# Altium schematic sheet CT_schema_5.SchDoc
size 582 x 363 mm
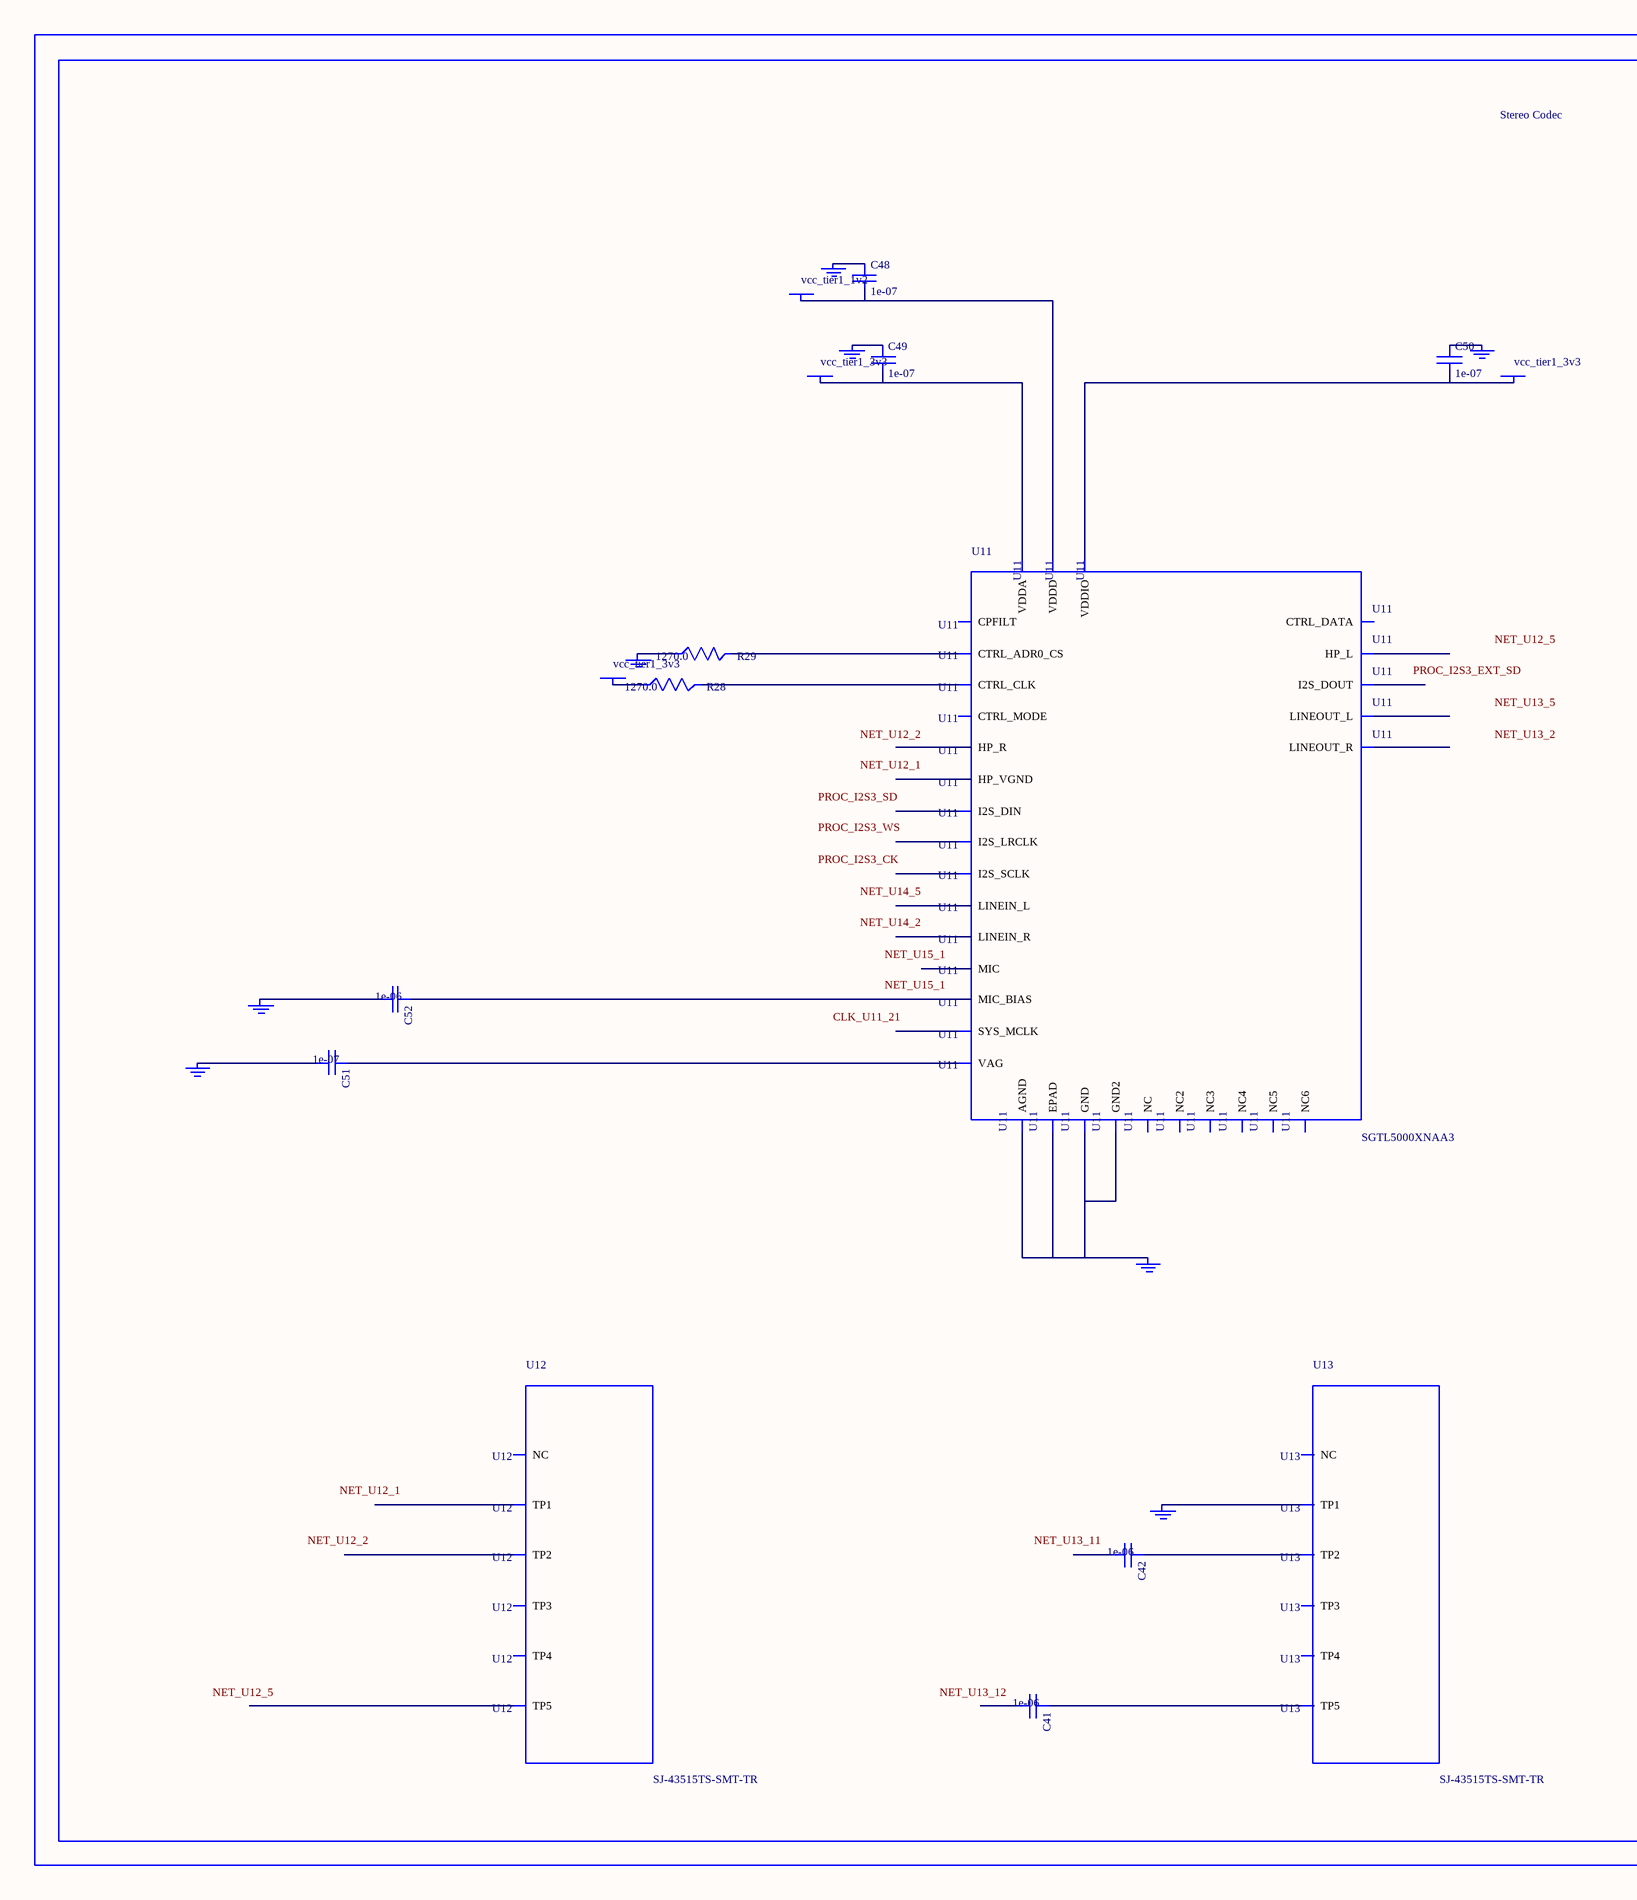
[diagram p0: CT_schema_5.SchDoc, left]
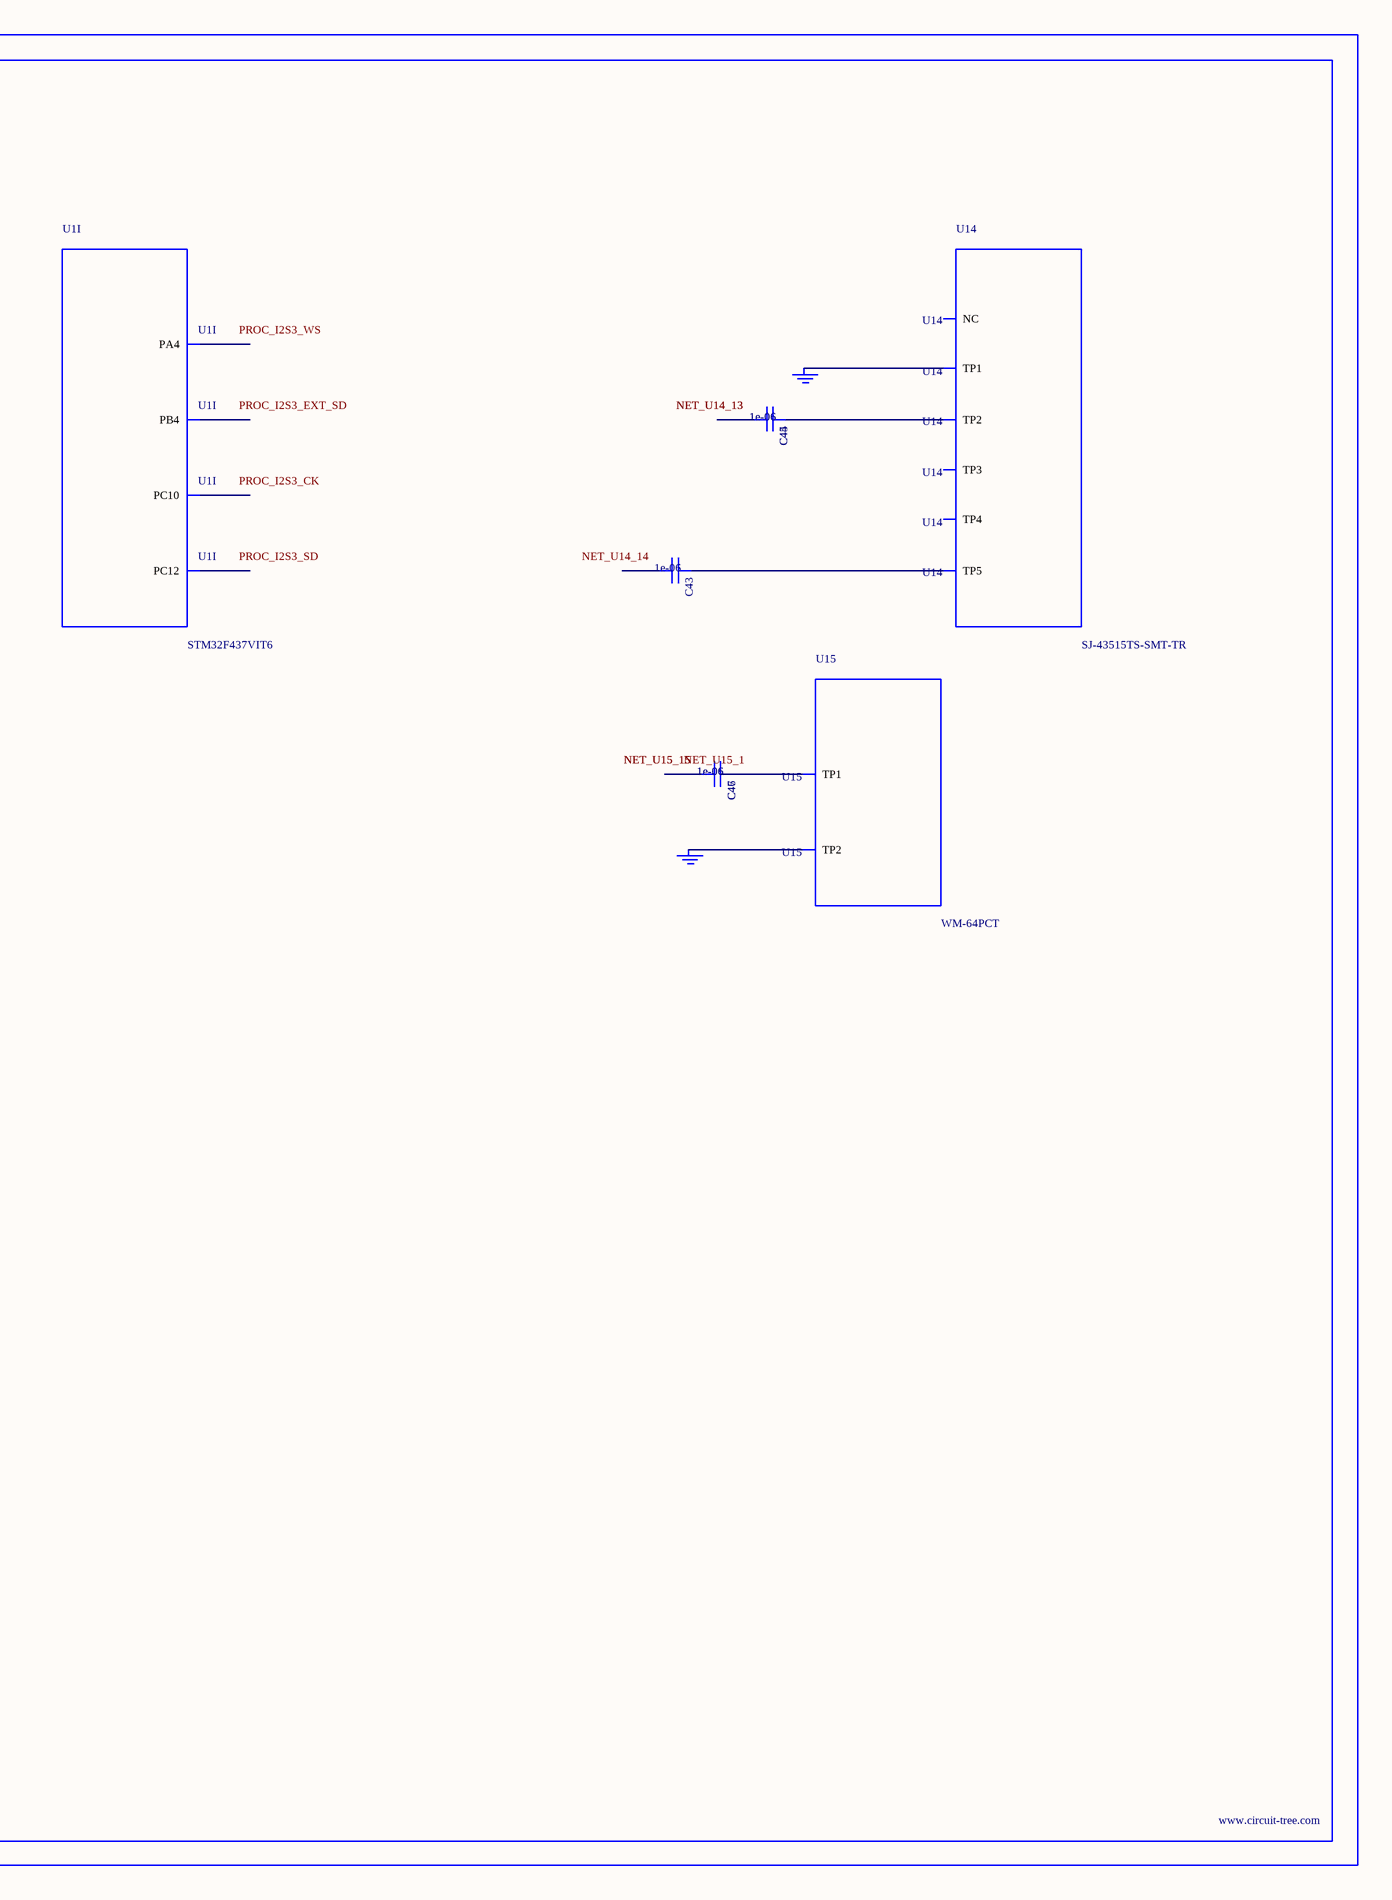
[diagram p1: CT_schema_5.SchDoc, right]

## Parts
BORDER4  (no value)
C41  1e-06  [C0603]
C42  1e-06  [C0603]
C43  1e-06  [C0603]
C44  1e-06  [C0603]
C45  1e-06  [C0603]
C46  1e-06  [C0603]
C47  1e-06  [C0603]
C48  1e-07  [C0402]
C49  1e-07  [C0402]
C50  1e-07  [C0402]
C51  1e-07  [C0402]
C52  1e-06  [C0603]
GND_INSTANCE_4_0  (no value)
GND_INSTANCE_4_1  (no value)
GND_INSTANCE_4_2  (no value)
GND_INSTANCE_4_3  (no value)
GND_INSTANCE_4_4  (no value)
GND_INSTANCE_4_5  (no value)
GND_INSTANCE_4_6  (no value)
GND_INSTANCE_4_7  (no value)
GND_INSTANCE_4_8  (no value)
GND_INSTANCE_4_9  (no value)
GND_INSTANCE_4_10  (no value)
POWER_INSTANCE_4_0  vcc_tier1_3v3
POWER_INSTANCE_4_1  vcc_tier1_3v3
POWER_INSTANCE_4_2  vcc_tier1_3v3
POWER_INSTANCE_4_3  vcc_tier1_1v2
R28  1270.0  [R0603]
R29  1270.0  [R0603]
U1  STM32F437VIT6  [LQFP100]  (part I of 9)
U11  SGTL5000XNAA3  [QFN-32]
U12  SJ-43515TS-SMT-TR  [SJ-43515TS-SMT-TR]
U13  SJ-43515TS-SMT-TR  [SJ-43515TS-SMT-TR]
U14  SJ-43515TS-SMT-TR  [SJ-43515TS-SMT-TR]
U15  WM-64PCT  [WM-64PC]

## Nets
NetC41_1: C41.1 U13.5(TP5)
NetC42_1: C42.1 U13.2(TP2)
NetC43_1: C43.1 U14.5(TP5)
NetC44_1: C44.1 C45.1 U14.2(TP2)
NetC44_2: C44.2 C45.2
NetC46_1: C46.1 C47.1 U15.1(TP1)
NetC46_2: C46.2 C47.2
NetC48_1: C48.1 GND_INSTANCE_4_5.0(GND)
NetC48_2: C48.2 POWER_INSTANCE_4_3.0(PWR) U11.30(VDDD)
NetC49_1: C49.1 GND_INSTANCE_4_1.0(GND)
NetC49_2: C49.2 POWER_INSTANCE_4_0.0(PWR) U11.5(VDDA)
NetC50_1: C50.1 GND_INSTANCE_4_4.0(GND)
NetC50_2: C50.2 POWER_INSTANCE_4_1.0(PWR) U11.20(VDDIO)
NetC51_1: C51.1 U11.10(VAG)
NetC51_2: C51.2 GND_INSTANCE_4_2.0(GND)
NetC52_1: C52.1 U11.16(MIC_BIAS)
NetC52_2: C52.2 GND_INSTANCE_4_3.0(GND)
NetGND_INSTANCE_4_0_0: GND_INSTANCE_4_0.0(GND) U11.1(GND) U11.3(GND2) U11.7(AGND) U11.EXP(EPAD)
NetGND_INSTANCE_4_6_0: GND_INSTANCE_4_6.0(GND) R29.1
NetGND_INSTANCE_4_7_0: GND_INSTANCE_4_7.0(GND) U13.1(TP1)
NetGND_INSTANCE_4_8_0: GND_INSTANCE_4_8.0(GND) GND_INSTANCE_4_9.0(GND) U14.1(TP1)
NetGND_INSTANCE_4_10_0: GND_INSTANCE_4_10.0(GND) U15.2(TP2)
NetPOWER_INSTANCE_4_2_0: POWER_INSTANCE_4_2.0(PWR) R28.1
NetR28_2: R28.2 U11.29(CTRL_CLK)
NetR29_2: R29.2 U11.31(CTRL_ADR0_CS)

Not connected (* = marked no-connect by the designer): C41 2; C42 2; C43 2; U1 29(PA4) 78(PC10) 80(PC12) 90(PB4); U11 2(HP_R) 4(HP_VGND) 6(HP_L) 8(NC) 9(NC2) 11(LINEOUT_R) 12(LINEOUT_L) 13(LINEIN_R) 14(LINEIN_L) 15(MIC) 17(NC3) 18(CPFILT) 19(NC4) 21(SYS_MCLK) 22(NC5) 23(I2S_LRCLK) 24(I2S_SCLK) 25(I2S_DOUT) 26(I2S_DIN) 27(CTRL_DATA) 28(NC6) 32(CTRL_MODE); U12 1(TP1) 2(TP2) 3(TP3) 4(TP4) 5(TP5) 6(NC); U13 3(TP3) 4(TP4) 6(NC); U14 3(TP3) 4(TP4) 6(NC)

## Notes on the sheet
- Labels drawn without touching a wire or pin: CLK_U11_21, NET_U12_1, NET_U12_2, NET_U12_5, NET_U13_2, NET_U13_5, NET_U13_11, NET_U13_12, NET_U14_2, NET_U14_5, NET_U14_14, NET_U15_1, PROC_I2S3_CK, PROC_I2S3_EXT_SD, PROC_I2S3_SD, PROC_I2S3_WS

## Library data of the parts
BORDER4 = BORDER_PAGE4
C41-C47 C52 = C0603C105K3RACTU
C48-C51 = C0402C104K3RACTU
GND_INSTANCE_4_0-GND_INSTANCE_4_10 = GND
POWER_INSTANCE_4_0-POWER_INSTANCE_4_3 = PWR
R28 R29 = RC0603FR-071K27L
